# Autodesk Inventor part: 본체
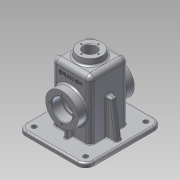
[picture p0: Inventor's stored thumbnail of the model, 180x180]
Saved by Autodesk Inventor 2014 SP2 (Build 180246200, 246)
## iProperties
Created: 2016-08
Part Number: 본체
Material: 알루미늄 6061
Document SubType Name: Modeling
Designer: user
Density: 2.71 g/cm^3
Appearance: 알루미늄 - 평지
Author: user
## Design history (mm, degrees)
sketch "스케치1"
  geometry: L1 (-57.5, 65)-(57.5, 65); L2 (57.5, 65)-(57.5, -65); L3 (57.5, -65)-(-57.5, -65); L4 (-57.5, -65)-(-57.5, 65); L5 (-57.5, 65)-(57.5, -65); L6 (57.5, 65)-(-57.5, -65); 1 further point
  constraints: 12 end point, 2 midpoint, 2 parallel, 1 horizontal, 1 perpendicular
  dimensions: "d0" = 115 distance of L2.end L3.end; "d1" = 130 distance of L1.end L2.end
extrude "돌출1" new body sketch "스케치1" distance "d2" = 10; taper "d3" = 0 deg
sketch "스케치2"
  geometry: L1 (-32.5, 32.5)-(32.5, 32.5); L2 (32.5, 32.5)-(32.5, -32.5); L3 (32.5, -32.5)-(-32.5, -32.5); L4 (-32.5, -32.5)-(-32.5, 32.5); L5 (-32.5, 32.5)-(32.5, -32.5); L6 (32.5, 32.5)-(-32.5, -32.5); 1 further point
  constraints: 12 end point, 2 midpoint, 2 parallel, 1 horizontal, 1 perpendicular
  dimensions: "d4" = 65 distance of L2.end L3.end; "d5" = 65 distance of L1.end L2.end
extrude "돌출2" join sketch "스케치2" distance "d6" = 100; taper "d7" = 0 deg
sketch "스케치3"
  geometry: L1 (90, -10)-(-25, -10) reference; C1 r 27.5 at (32.5, 45); 2 further points
  constraints: 1 centre point, 1 midpoint, 1 vertical alignment
  dimensions: "d8" = 55 diameter of C1; "d9" = 55 distance from line of L1 C1.centre
extrude "돌출3" join sketch "스케치3" distance "d10" = 15; taper "d11" = 0 deg
sketch "스케치4"
  geometry: L1 (-25, 10)-(90, 10) reference; C1 r 27.5 at (32.5, -45); 2 further points
  constraints: 1 centre point, 1 midpoint, 1 vertical alignment
  dimensions: "d12" = 55 diameter of C1; "d13" = 55 distance from line of L1 C1.centre
extrude "돌출4" join sketch "스케치4" distance "d14" = 15; taper "d15" = 0 deg
sketch "스케치7"
  geometry: C1 r 27.5 at (0, 0) reference; C2 r 17.5 at (0, 0); 1 further point
  constraints: 1 centre point, 1 coincident
  dimensions: "d23" = 35 diameter of C2
extrude "돌출7" cut sketch "스케치7" distance "d24" = 17; taper "d25" = 0 deg
sketch "스케치8"
  geometry: C1 r 17.5 at (0, 0) reference; C2 r 17.5 at (0, 0); 1 further point
  constraints: 1 centre point, 1 coincident
  dimensions: "d26" = 35 diameter of C2
extrude "돌출8" cut sketch "스케치8" distance "d27" = 17; taper "d28" = 0 deg
sketch "스케치9"
  geometry: C1 r 17.5 at (0, 0) reference; C2 r 15 at (0, 0); 1 further point
  constraints: 1 centre point, 1 coincident
  dimensions: "d29" = 30 diameter of C2
extrude "돌출9" cut sketch "스케치9" stored distance "d30" = 17; taper "d31" = 0 deg
sketch "스케치11" dims "d35" = 42
  geometry: C1 r 17.5 at (0, 0) reference; C2 r 27.5 at (0, 0) reference; 6 further points
  constraints: 2 vertical alignment, 1 coincident, 7 other
  dimensions: "d38" = 360 deg dimension on C1.centre point (0, 21) (derived)
hole "구멍1" sketch "스케치11" at (0, 21), (-21, 0), (0, -21), (21, 0) diameter "d40" = 3.242; stored, may be unused: countersink angle "d44" = 90 deg, drill point angle "d46" = 118 deg; dims "d41" = 8, "d42" = 4, "d43" = 2, "d45" = 10
sketch "스케치12" dims "d47" = 42
  geometry: C1 r 17.5 at (0, 0) reference; C2 r 27.5 at (0, 0) reference; 6 further points
  constraints: 2 vertical alignment, 1 coincident, 7 other
  dimensions: "d50" = 360 deg dimension on C1.centre point (0, -21) (derived)
hole "구멍2" sketch "스케치12" at (0, -21), (21, 0), (0, 21), (-21, 0) diameter "d52" = 3.242; stored, may be unused: countersink angle "d56" = 90 deg, drill point angle "d58" = 118 deg; dims "d53" = 8, "d54" = 4, "d55" = 2, "d57" = 10
sketch "스케치14"
  geometry: L1 (-32.5, 10)-(-32.5, 110) reference; L2 (32.5, 10)-(32.5, 110) reference; L3 (-57.5, 10)-(57.5, 10) reference; L4 (-32.5, 70)-(-41.068, 70); L5 (-41.068, 70)-(-49.5, 10); L6 (-57.5, 0)-(-57.5, 10) reference; 1 further point
  constraints: 4 end point, 2 point on line, 1 parallel
  dimensions: "d71" = 8 distance of L5.end L3.start; "d72" = 8 deg angle of L5 L6; "d73" = 70 distance from line of L4 L6.start
feature "리브1" sketch "스케치14" dims "d74" = 1, "d75" = 10, "d76" = 0, "d77" = 0, "d78" = 1, "d79" = 1
sketch "스케치15"
  geometry: L1 (-32.5, 27.5)-(-47.5, 27.5) reference; L2 (-32.5, 10)-(-32.5, 110) reference; L3 (65, 10)-(-65, 10) reference; L4 (-42.5, 27.5)-(-42.5, 10); 1 further point
  constraints: 2 end point, 2 point on line, 1 perpendicular
feature "리브2" sketch "스케치15" dims "d81" = 1, "d82" = 6, "d83" = 0, "d84" = 0, "d85" = 1, "d86" = 1
sketch "스케치16"
  geometry: L1 (52.5, -60)-(-52.5, -60); L2 (-52.5, -60)-(-52.5, 60); L3 (-52.5, 60)-(52.5, 60); L4 (52.5, 60)-(52.5, -60); L5 (52.5, -60)-(-52.5, 60); L6 (-52.5, -60)-(52.5, 60); L7 (-57.5, -65)-(57.5, -65) reference; L8 (57.5, -65)-(57.5, 65) reference; L9 (57.5, 65)-(-57.5, 65) reference; L10 (-57.5, 65)-(-57.5, -65) reference; 1 further point
  constraints: 12 end point, 2 midpoint, 2 parallel, 1 horizontal, 1 perpendicular
  dimensions: "d87" = 105 distance of L2.end L3.end; "d88" = 120 distance of L1.end L2.end
extrude "돌출11" cut sketch "스케치16" distance "d89" = 3; taper "d90" = 0 deg
chamfer "모따기1" distance "d91" = 1; stored, may be unused: second distance "d92" = 2, angle "d93" = 45 deg
chamfer "모따기2" distance "d94" = 1; stored, may be unused: second distance "d95" = 2, angle "d96" = 45 deg
fillet "모깎기1" dims "d100" = 14
fillet "모깎기2" dims "d101" = 3
hole "구멍4" diameter "d104" = 8; stored, may be unused: countersink angle "d108" = 90 deg, drill point angle "d110" = 118 deg; dims "d105" = 7, "d106" = 4, "d107" = 2, "d109" = 9, "d111" = 10, "d112" = 10
hole "구멍5" diameter "d115" = 8; stored, may be unused: countersink angle "d119" = 90 deg, drill point angle "d121" = 118 deg; dims "d113" = 10, "d114" = 10, "d116" = 7, "d117" = 4, "d118" = 2, "d120" = 9
hole "구멍6" diameter "d124" = 8; stored, may be unused: countersink angle "d128" = 90 deg, drill point angle "d130" = 118 deg; dims "d122" = 10, "d123" = 10, "d125" = 7, "d126" = 4, "d127" = 2, "d129" = 9
hole "구멍7" diameter "d133" = 8; stored, may be unused: countersink angle "d137" = 90 deg, drill point angle "d139" = 118 deg; dims "d131" = 10, "d132" = 10, "d134" = 7, "d135" = 4, "d136" = 2, "d138" = 9
fillet "모깎기3" dims "d140" = 8
fillet "모깎기4" dims "d141" = 9
fillet "모깎기6" dims "d143" = 3
fillet "모깎기7" dims "d144" = 3
fillet "모깎기9" dims "d146" = 0.3
fillet "모깎기10" dims "d147" = 3
fillet "모깎기11" dims "d148" = 3
fillet "모깎기12" dims "d149" = 3
fillet "모깎기13" dims "d150" = 3
fillet "모깎기14" dims "d151" = 3
fillet "모깎기15" dims "d152" = 3
fillet "모깎기16" dims "d153" = 1
node "작업 평면1"
node "작업 평면2"
sketch "스케치18"
  geometry: C1 r 20 at (0, 0); 1 further point
  constraints: 1 centre point, 1 coincident
  dimensions: "d160" = 40 diameter of C1
extrude "돌출12" join sketch "스케치18" stored distance "d161" = 3; taper "d162" = 7 deg
sketch "스케치19"
  geometry: C1 r 10.5 at (0, 0); 1 further point
  constraints: 1 centre point, 1 coincident
  dimensions: "d163" = 21 diameter of C1
extrude "돌출13" cut sketch "스케치19" stored distance "d164" = 3; taper "d165" = 0 deg
sketch "스케치20" dims "d166" = 29
  geometry: 6 further points
  constraints: 2 vertical alignment, 1 coincident, 7 other
  dimensions: "d169" = 360 deg dimension on point (0, 0) point (0, 14.5) (derived)
hole "구멍8" sketch "스케치20" at (0, 14.5), (-14.5, 0), (0, -14.5), (14.5, 0) diameter "d171" = 2.459; stored, may be unused: countersink angle "d175" = 90 deg, drill point angle "d177" = 118 deg; dims "d172" = 7, "d173" = 4, "d174" = 2, "d176" = 9
fillet "모깎기17" dims "d178" = 3
chamfer "모따기4" distance "d179" = 1; stored, may be unused: second distance "d180" = 2, angle "d181" = 45 deg
sketch "스케치21"
  geometry: L1 (-27.5, 105)-(27.5, 105); L2 (27.5, 105)-(27.5, 0); L3 (27.5, 0)-(-27.5, 0); L4 (-27.5, 0)-(-27.5, 105); L5 (32.5, 102)-(32.5, 73.166) reference; L6 (-32.5, 73.166)-(-32.5, 102) reference; L7 (-24.5, 110)-(24.5, 110) reference; 2 further points
  constraints: 8 end point, 2 parallel, 1 coincident, 1 horizontal, 1 midpoint, 1 perpendicular
  dimensions: "d182" = 5 distance between parallel lines of L5 L2; "d183" = 5 distance between parallel lines of L7 L1
extrude "돌출14" cut sketch "스케치21" stored distance "d184" = 55; taper "d185" = 0 deg
sketch "스케치22"
  geometry: L1 (-20, 120)-(20, 120) reference; L2 (32.5, 11)-(32.5, 102) reference; L3 (-32.5, 102)-(-32.5, 11) reference; 2 further points
  constraints: 1 other
  dimensions: "d186" = 26 distance from line of point (0, 94) L1; "d187" = 32.5 distance from line of point (0, 94) L3
feature "엠보싱2" sketch "스케치22" dims "d188" = 0.5, "d189" = 0
fillet "모깎기18" dims "d190" = 3
node "솔리드1"
mirror "대칭1"
mirror "대칭2"
node "투영된 루프1"
node "투영된 루프2"
node "투영된 루프3"
node "투영된 루프4"
other parameters: "d154" = -42
